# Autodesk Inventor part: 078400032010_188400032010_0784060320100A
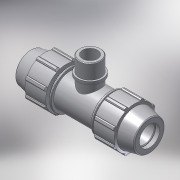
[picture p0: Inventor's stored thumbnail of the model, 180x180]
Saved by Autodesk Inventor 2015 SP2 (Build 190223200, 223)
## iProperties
Created: 2017-02
Part Number: 078400032010_188400032010_0784060320100A
Material: PVC-Piping
Description: PLASSON TEE WITH THREADED MALE OFFTAKE 32-1"-32
Document SubType Name: Modeling
Designer: KIM
Mass: 92.6774 g
Surface Area: 199.44 cm^2
Volume: 66.1981 cm^3
Density: 1.4 g/cm^3
Appearance: Smooth - White
Author: Кирилл
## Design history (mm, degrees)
derived "07840.ipt"
feature "Solid1::07840.ipt"
feature "Solid2::07840.ipt"
tag "TaggingFeature1"
body "Solid1"
body "Solid2"
other parameters: "d2" = 32, "d4" = 7.08333, "d5" = 20.4, "d7" = 64, "d11" = 2.83333, "d13" = 120 deg, "d14" = 48, "d15" = 12 deg, "d16" = 55.68, "d18" = 1.6, "d19" = 35 deg, "d20" = 17.5 deg, "d21" = 59.52, "d23" = 0, "d25" = 360 deg, "d27" = 1.28, "d33" = 0.64, "d42" = 30.6, "d43" = 1.92, "d46" = 0.96, "d68" = 2.83333, "d72" = 58, "d73" = 33.249, "d75" = 38.23635, "d76" = 23.2743, "d77" = 24, "d80" = 0.99747, "d91" = 48, "d93" = 67, "d95" = 28.8, "d101" = 0, "d103" = 0, "d105" = 0, "d_" = 32, "E_" = 64, "A_" = 58, "l_" = 67, "R_" = 33.249
